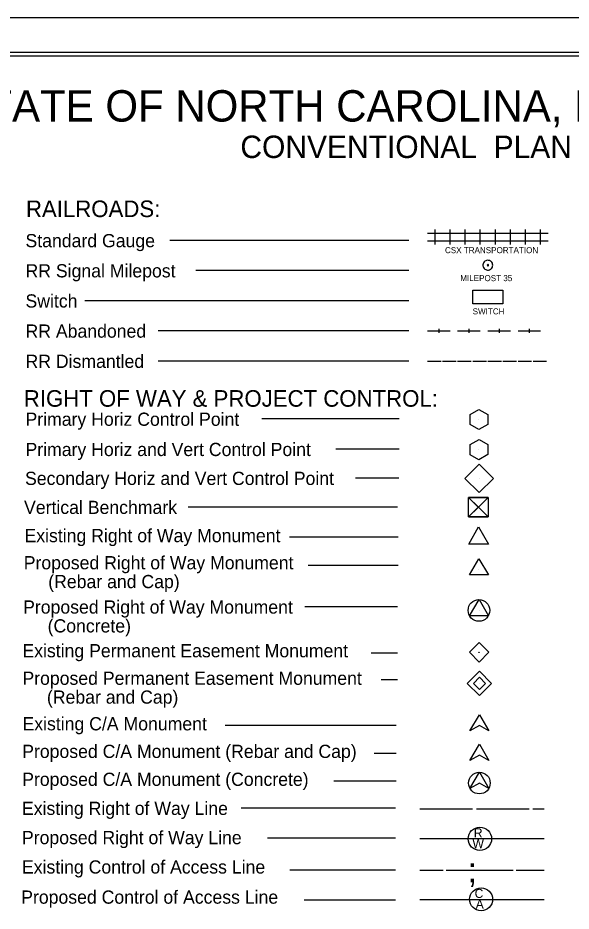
# Model space of a CAD drawing. Extents: x 2594871.4 to 2594905.1, y 784137.6 to 784159.6.
# Drawn here: x 2594882.63 to 2594889.82, y 784147.95 to 784159.56 of the extents above; entities that cross this region are included whole.
import ezdxf

# ---------------------------------------------------------------- set-up
doc = ezdxf.new("R2010")
doc.units = 0
for name, color, linetype in [('Default', 7, 'Continuous'), ('Sheet Plot Border Inside CELL', 7, 'Continuous'), ('Sheet Plot Border Outside CELL', 7, 'Continuous'), ('Sheet Symbology CELL', 7, 'Continuous')]:
    doc.layers.add(name, color=color, linetype=linetype)

msp = doc.modelspace()

# ---------------------------------------------------------------- linework, layer by layer
at = {"layer": 'Default'}
for p, q in [((2594888.052, 784156.615), (2594888.052, 784156.811)), ((2594888.248, 784156.615), (2594888.248, 784156.811)), ((2594888.444, 784156.615), (2594888.444, 784156.811)), ((2594888.64, 784156.615), (2594888.64, 784156.811)), ((2594888.837, 784156.615), (2594888.837, 784156.811)), ((2594889.033, 784156.615), (2594889.033, 784156.811)), ((2594889.229, 784156.615), (2594889.229, 784156.811)), ((2594889.425, 784156.615), (2594889.425, 784156.811)), ((2594887.954, 784156.762), (2594888.15, 784156.762)), ((2594888.15, 784156.762), (2594888.346, 784156.762)), ((2594888.346, 784156.762), (2594888.542, 784156.762)), ((2594888.542, 784156.762), (2594888.738, 784156.762)), ((2594888.738, 784156.762), (2594888.935, 784156.762)), ((2594888.935, 784156.762), (2594889.131, 784156.762)), ((2594889.131, 784156.762), (2594889.327, 784156.762)), ((2594889.327, 784156.762), (2594889.523, 784156.762)), ((2594887.711, 784156.668), (2594884.603, 784156.668)), ((2594887.954, 784156.664), (2594888.15, 784156.664)), ((2594888.15, 784156.664), (2594888.346, 784156.664)), ((2594888.346, 784156.664), (2594888.542, 784156.664)), ((2594888.542, 784156.664), (2594888.738, 784156.664)), ((2594888.738, 784156.664), (2594888.935, 784156.664)), ((2594888.935, 784156.664), (2594889.131, 784156.664)), ((2594889.131, 784156.664), (2594889.327, 784156.664)), ((2594889.327, 784156.664), (2594889.523, 784156.664)), ((2594887.711, 784156.276), (2594884.94, 784156.276)), ((2594887.711, 784155.884), (2594883.495, 784155.884)), ((2594887.711, 784155.491), (2594884.451, 784155.491)), ((2594887.954, 784155.491), (2594888.248, 784155.491)), ((2594888.101, 784155.516), (2594888.101, 784155.467)), ((2594888.346, 784155.491), (2594888.64, 784155.491)), ((2594888.493, 784155.516), (2594888.493, 784155.467)), ((2594888.738, 784155.491), (2594889.033, 784155.491)), ((2594888.886, 784155.516), (2594888.886, 784155.467)), ((2594889.131, 784155.491), (2594889.425, 784155.491)), ((2594889.278, 784155.516), (2594889.278, 784155.467)), ((2594887.711, 784155.099), (2594884.451, 784155.099)), ((2594887.954, 784155.099), (2594888.13, 784155.099)), ((2594888.15, 784155.099), (2594888.327, 784155.099)), ((2594888.346, 784155.099), (2594888.523, 784155.099)), ((2594888.542, 784155.099), (2594888.719, 784155.099)), ((2594888.738, 784155.099), (2594888.915, 784155.099)), ((2594888.935, 784155.099), (2594889.111, 784155.099)), ((2594889.131, 784155.099), (2594889.307, 784155.099)), ((2594889.327, 784155.099), (2594889.503, 784155.099)), ((2594887.585, 784154.346), (2594885.799, 784154.346)), ((2594888.623, 784154.339), (2594888.623, 784154.339)), ((2594887.585, 784153.954), (2594886.763, 784153.954)), ((2594888.623, 784153.947), (2594888.623, 784153.947)), ((2594887.579, 784153.577), (2594887.019, 784153.577)), ((2594888.626, 784153.573), (2594888.626, 784153.573)), ((2594887.565, 784153.2), (2594884.842, 784153.2)), ((2594888.616, 784153.2), (2594888.616, 784153.2)), ((2594887.571, 784152.808), (2594886.158, 784152.808)), ((2594887.573, 784152.439), (2594886.402, 784152.439)), ((2594888.623, 784152.388), (2594888.623, 784152.388)), ((2594887.564, 784151.902), (2594886.358, 784151.902)), ((2594888.624, 784151.857), (2594888.624, 784151.857)), ((2594887.565, 784151.3), (2594887.221, 784151.3)), ((2594888.625, 784151.313), (2594888.625, 784151.313)), ((2594887.565, 784150.954), (2594887.353, 784150.954)), ((2594888.629, 784150.909), (2594888.629, 784150.909)), ((2594888.506, 784150.289), (2594888.628, 784150.501)), ((2594888.628, 784150.501), (2594888.751, 784150.289)), ((2594887.546, 784150.362), (2594885.324, 784150.362)), ((2594888.628, 784150.36), (2594888.506, 784150.289)), ((2594888.751, 784150.289), (2594888.628, 784150.36)), ((2594888.505, 784149.904), (2594888.628, 784150.116)), ((2594888.628, 784150.116), (2594888.75, 784149.904)), ((2594887.548, 784149.998), (2594887.262, 784149.998)), ((2594888.628, 784149.975), (2594888.505, 784149.904)), ((2594888.75, 784149.904), (2594888.628, 784149.975)), ((2594888.505, 784149.541), (2594888.628, 784149.753)), ((2594888.628, 784149.753), (2594888.75, 784149.541)), ((2594887.548, 784149.635), (2594886.736, 784149.635)), ((2594888.628, 784149.612), (2594888.505, 784149.541)), ((2594888.75, 784149.541), (2594888.628, 784149.612)), ((2594887.539, 784149.286), (2594885.528, 784149.286)), ((2594887.853, 784149.275), (2594888.54, 784149.275)), ((2594888.589, 784149.275), (2594889.276, 784149.275)), ((2594889.325, 784149.275), (2594889.472, 784149.275)), ((2594887.539, 784148.894), (2594885.871, 784148.894)), ((2594887.853, 784148.891), (2594889.472, 784148.891)), ((2594887.539, 784148.48), (2594886.161, 784148.48)), ((2594887.853, 784148.48), (2594888.157, 784148.48)), ((2594888.196, 784148.48), (2594889.067, 784148.48)), ((2594889.106, 784148.48), (2594889.472, 784148.48)), ((2594887.853, 784148.098), (2594889.472, 784148.098)), ((2594887.539, 784148.091), (2594886.348, 784148.091))]:
    msp.add_line(p, q, dxfattribs=at)
for points in [[(2594888.802, 784156.346), (2594888.801, 784156.359), (2594888.797, 784156.371), (2594888.791, 784156.383), (2594888.782, 784156.392), (2594888.772, 784156.399), (2594888.76, 784156.406), (2594888.749, 784156.408), (2594888.735, 784156.409), (2594888.722, 784156.407), (2594888.711, 784156.403), (2594888.699, 784156.397), (2594888.69, 784156.388), (2594888.683, 784156.376), (2594888.678, 784156.365), (2594888.675, 784156.352), (2594888.675, 784156.339), (2594888.678, 784156.327), (2594888.683, 784156.315), (2594888.69, 784156.304), (2594888.699, 784156.295), (2594888.711, 784156.288), (2594888.722, 784156.285), (2594888.735, 784156.282), (2594888.749, 784156.283), (2594888.76, 784156.286), (2594888.772, 784156.292), (2594888.782, 784156.3), (2594888.791, 784156.309), (2594888.797, 784156.32), (2594888.801, 784156.333), (2594888.802, 784156.346)], [(2594888.741, 784156.353), (2594888.737, 784156.353), (2594888.734, 784156.351), (2594888.731, 784156.347), (2594888.732, 784156.343), (2594888.735, 784156.339), (2594888.739, 784156.338), (2594888.743, 784156.339), (2594888.745, 784156.342), (2594888.746, 784156.347), (2594888.745, 784156.351), (2594888.741, 784156.353)], [(2594888.623, 784154.208), (2594888.51, 784154.273), (2594888.51, 784154.403), (2594888.623, 784154.469), (2594888.737, 784154.405), (2594888.737, 784154.273), (2594888.623, 784154.208)], [(2594888.743, 784153.327), (2594888.489, 784153.073), (2594888.616, 784153.2), (2594888.743, 784153.073), (2594888.489, 784153.327)], [(2594888.616, 784153.2), (2594888.743, 784153.327), (2594888.489, 784153.327), (2594888.616, 784153.2)], [(2594888.616, 784153.2), (2594888.489, 784153.073), (2594888.743, 784153.073), (2594888.616, 784153.2)], [(2594888.491, 784152.72), (2594888.618, 784152.942), (2594888.745, 784152.72), (2594888.491, 784152.72)]]:
    msp.add_lwpolyline(points, dxfattribs=at)
for points in [[(2594888.542, 784156.02), (2594888.935, 784156.02), (2594888.935, 784155.842), (2594888.542, 784155.842)], [(2594888.509, 784154.013), (2594888.624, 784154.077), (2594888.739, 784154.014), (2594888.737, 784153.882), (2594888.622, 784153.815), (2594888.509, 784153.88)], [(2594888.441, 784153.573), (2594888.627, 784153.759), (2594888.813, 784153.573), (2594888.627, 784153.388)], [(2594888.489, 784153.327), (2594888.743, 784153.327), (2594888.743, 784153.073), (2594888.489, 784153.073)], [(2594888.501, 784152.318), (2594888.623, 784152.529), (2594888.746, 784152.318)], [(2594888.501, 784151.787), (2594888.624, 784151.999), (2594888.746, 784151.787)], [(2594888.498, 784151.313), (2594888.625, 784151.44), (2594888.752, 784151.313), (2594888.625, 784151.185)], [(2594888.629, 784151.066), (2594888.787, 784150.908), (2594888.629, 784150.751), (2594888.471, 784150.908)], [(2594888.629, 784150.987), (2594888.708, 784150.908), (2594888.629, 784150.83), (2594888.55, 784150.908)]]:
    msp.add_lwpolyline(points, close=True, dxfattribs=at)
for centre, radius in [((2594888.623, 784151.857), 0.141), ((2594888.625, 784151.313), 0.00248), ((2594888.628, 784149.612), 0.141), ((2594888.635, 784148.887), 0.152), ((2594888.651, 784148.1), 0.149)]:
    msp.add_circle(centre, radius, dxfattribs=at)
at = {"layer": 'Sheet Plot Border Inside CELL'}
msp.add_lwpolyline([(2594871.632, 784138.011), (2594904.962, 784138.011), (2594904.962, 784159.113), (2594871.632, 784159.113)], close=True, dxfattribs=at)
at = {"layer": 'Sheet Plot Border Outside CELL'}
msp.add_lwpolyline([(2594905.052, 784159.562), (2594871.372, 784159.562), (2594871.372, 784137.562), (2594905.052, 784137.562)], close=True, dxfattribs=at)
at = {"layer": 'Sheet Symbology CELL'}
msp.add_lwpolyline([(2594904.712, 784159.062), (2594874.712, 784159.062), (2594874.712, 784138.082), (2594904.712, 784138.082)], close=True, dxfattribs=at)

# ---------------------------------------------------------------- texts
at = {"layer": 'Default'}
for s, height, p in [('STATE OF NORTH CAROLINA, DIVISION OF HIGHWAYS', 0.40827, (2594881.853, 784158.213)), ('CONVENTIONAL  PLAN SHEET SYMBOLS', 0.29162, (2594885.52, 784157.739)), ('RAILROADS:', 0.2158, (2594882.731, 784156.971)), ('Standard Gauge', 0.17164, (2594882.725, 784156.579)), ('CSX TRANSPORTATION', 0.07846, (2594888.181, 784156.502)), ('RR Signal Milepost', 0.17164, (2594882.725, 784156.187)), ('MILEPOST 35', 0.07846, (2594888.38, 784156.138)), ('Switch', 0.1716, (2594882.725, 784155.795)), ('SWITCH', 0.0785, (2594888.541, 784155.706)), ('RR Abandoned', 0.17164, (2594882.725, 784155.403)), ('RR Dismantled', 0.17164, (2594882.725, 784155.01)), ('RIGHT OF WAY & PROJECT CONTROL:', 0.21577, (2594882.703, 784154.505)), ('Primary Horiz Control Point', 0.17164, (2594882.725, 784154.257)), ('Primary Horiz and Vert Control Point', 0.17164, (2594882.725, 784153.864)), ('Secondary Horiz and Vert Control Point', 0.17164, (2594882.719, 784153.488)), ('Vertical Benchmark', 0.17164, (2594882.706, 784153.111)), ('Existing Right of Way Monument', 0.17164, (2594882.712, 784152.744)), ('Proposed Right of Way Monument', 0.17164, (2594882.702, 784152.391)), ('     (Rebar and Cap)', 0.17164, (2594882.702, 784152.146)), ('Proposed Right of Way Monument', 0.17164, (2594882.694, 784151.815)), ('     (Concrete)', 0.17164, (2594882.694, 784151.57)), ('Existing Permanent Easement Monument', 0.17164, (2594882.685, 784151.247)), ('Proposed Permanent Easement Monument', 0.17164, (2594882.685, 784150.889)), ('     (Rebar and Cap)', 0.17164, (2594882.685, 784150.644)), ('Existing C/A Monument', 0.17164, (2594882.686, 784150.297)), ('Proposed C/A Monument (Rebar and Cap)', 0.17164, (2594882.682, 784149.938)), ('Proposed C/A Monument (Concrete)', 0.17164, (2594882.682, 784149.575)), ('Existing Right of Way Line', 0.17164, (2594882.679, 784149.197)), ('R', 0.119, (2594888.555, 784148.905)), ('Proposed Right of Way Line', 0.17164, (2594882.679, 784148.817)), ('W', 0.119, (2594888.538, 784148.765)), ('Existing Control of Access Line', 0.17164, (2594882.679, 784148.435)), (';', 0.324, (2594888.477, 784148.319)), ('Proposed Control of Access Line', 0.17164, (2594882.669, 784148.043)), ('C', 0.117, (2594888.567, 784148.118)), ('A', 0.117, (2594888.581, 784147.978))]:
    msp.add_text(s, height=height, rotation=360, dxfattribs=at).set_placement(p)

doc.saveas('drawing.dxf')
